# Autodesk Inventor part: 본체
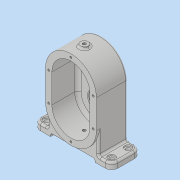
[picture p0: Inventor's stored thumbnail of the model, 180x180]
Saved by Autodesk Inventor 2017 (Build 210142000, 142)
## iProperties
Part Number: 본체
Material: 일반
Document SubType Name: Modeling
Designer: MRC
Density: 1 g/cm^3
Appearance: 기본값
Author: MRC
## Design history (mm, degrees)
sketch "스케치1"
  geometry: L1 (0, 0)-(0, 45); L2 (-40, 0)-(-40, 45); L3 (40, 45)-(40, 0); A1 r 40 centre (0, 0) between (-40, 0) and (40, 0); A2 r 40 centre (0, 45) between (40, 45) and (-40, 45); 1 further point
  constraints: 8 end point, 4 point on circle, 4 tangent, 2 centre point, 1 midpoint, 1 parallel, 1 vertical
  dimensions: "d0" = 45 distance of L1.start L1.end; "d1" = 80 distance between parallel lines of L3 L2
extrude "돌출1" new body sketch "스케치1" stored distance "d2" = 49; taper "d3" = 0 deg
sketch "스케치2"
  geometry: L1 (0, 45)-(0, 0); L2 (-26, 45)-(-26, 0); L3 (26, 0)-(26, 45); A1 r 40 centre (0, 45) between (40, 45) and (-40, 45) reference; A2 r 40 centre (0, 0) between (-40, 0) and (40, 0) reference; A3 r 26 centre (0, 45) between (26, 45) and (-26, 45); A4 r 26 centre (0, 0) between (-26, 0) and (26, 0); 1 further point
  constraints: 8 end point, 4 point on circle, 4 tangent, 2 centre point, 1 midpoint, 1 parallel, 1 vertical
  dimensions: "d4" = 52 distance between parallel lines of L3 L2
extrude "돌출2" join sketch "스케치2" distance "d5" = 8; taper "d6" = 0 deg
sketch "스케치3"
  geometry: L1 (0, 0)-(0, 45); L2 (-26, 0)-(-26, 15); L3 (26, 15)-(26, 0); L4 (-26, 0)-(-26, 45) reference; L5 (-26, 15)-(26, 15); L6 (26, 45)-(26, 0) reference; A1 r 26 centre (0, 0) between (-26, 0) and (26, 0) reference; A2 r 26 centre (0, 0) between (-26, 0) and (26, 0); 1 further point
  constraints: 10 end point, 2 point on circle, 2 point on line, 2 tangent, 1 centre point, 1 midpoint, 1 parallel, 1 vertical
  dimensions: "d7" = 30 distance from line of L1.end L5; "d8" = 52 distance of L2.end L3.start
extrude "돌출3" join sketch "스케치3" distance "d9" = 3; taper "d10" = 0 deg
node "작업 평면1"
sketch "스케치4"
  geometry: L1 (40, 24.5)-(-40, 24.5) reference; C1 r 6 at (0, 3.5); 1 further point
  constraints: 1 centre point, 1 vertical alignment
  dimensions: "d12" = 12 diameter of C1; "d14" = 21 distance from line of L1 C1.centre
extrude "돌출4" join sketch "스케치4" stored distance "d15" = 3; taper "d16" = 0 deg
sketch "스케치6"
  geometry: L1 (-40, 45)-(-40, 0) reference; L2 (40, 0)-(40, 45) reference; L3 (-30, 45)-(-30, 0); L4 (30, 0)-(30, 45); A1 r 40 centre (0, 0) between (-40, 0) and (40, 0) reference; A2 r 40 centre (0, 45) between (40, 45) and (-40, 45) reference; A3 r 30 centre (0, 0) between (-30, 0) and (30, 0); A4 r 30 centre (0, 45) between (30, 45) and (-30, 45)
  constraints: 4 end point, 4 point on circle, 2 centre point, 3 other
  dimensions: "d22" = 30 radius of A4
extrude "돌출5" cut sketch "스케치6" distance "d23" = 41; taper "d24" = 0 deg
hole "구멍1" diameter "d27" = 22; stored, may be unused: countersink angle "d31" = 90 deg, drill point angle "d33" = 118 deg; dims "d25" = 10, "d26" = 10, "d28" = 6, "d29" = 28, "d30" = 8, "d32" = 8
hole "구멍2" diameter "d36" = 20; stored, may be unused: countersink angle "d40" = 90 deg, drill point angle "d42" = 0 deg; dims "d34" = 10, "d35" = 10, "d37" = 6, "d38" = 28, "d39" = 8, "d41" = 12
sketch "스케치7"
  geometry: C1 r 11 at (0, 45) reference; C2 r 14 at (0, 45); A1 r 26 centre (0, 45) between (26, 45) and (-26, 45) reference; 1 further point
  constraints: 1 centre point, 1 coincident
  dimensions: "d43" = 28 diameter of C2
extrude "돌출6" cut sketch "스케치7" distance "d44" = 4; taper "d45" = 0 deg
sketch "스케치8"
  geometry: C1 r 14 at (0, 45) reference; A1 r 40 centre (0, 45) between (40, 45) and (-40, 45) reference; 2 further points
  constraints: 1 vertical alignment
  dimensions: "d46" = 20 distance of A1.centre point (0, 65)
hole "구멍3" sketch "스케치8" at (0, 65) diameter "d47" = 3.242; stored, may be unused: countersink angle "d51" = 90 deg, drill point angle "d53" = 118 deg; dims "d48" = 8, "d49" = 28, "d50" = 8, "d52" = 10
hole "구멍4" diameter "d59" = 4.917; stored, may be unused: countersink angle "d63" = 90 deg, drill point angle "d65" = 118 deg; dims "d57" = 10, "d58" = 10, "d60" = 12, "d61" = 28, "d62" = 8, "d64" = 17.1
sketch "스케치9"
  geometry: L1 (40, 0)-(40, 45) reference; L2 (-40, 45)-(-40, 0) reference; L3 (-40, 0)-(-40, -37); L4 (-40, -37)-(-61, -37); L5 (-61, -37)-(-61, -47); L6 (-61, -47)-(-35, -47); L7 (-35, -47)-(-35, -42); L8 (-35, -42)-(35, -42); L9 (35, -42)-(35, -47); L10 (35, -47)-(61, -47); L11 (61, -47)-(61, -37); L12 (61, -37)-(40, -37); L13 (40, -37)-(40, 0); A1 r 26 centre (0, 0) between (-26, 0) and (26, 0) reference; A2 r 40 centre (0, 0) between (-40, 0) and (40, 0) reference
  constraints: 22 end point, 8 perpendicular, 4 collinear, 4 point on line, 2 point on circle, 1 vertical
  dimensions: "d66" = 70 distance of L7.end L8.end; "d67" = 47 distance from line of L6 A1.centre; "d68" = 10 distance of L4.end L5.end; "d69" = 5 distance of L6.end L7.end; "d70" = 122 distance between parallel lines of L11 L5
extrude "돌출7" join sketch "스케치9" distance "d71" = 46; taper "d72" = 0 deg
fillet "모깎기1" dims "d73" = 10
hole "구멍5" diameter "d76" = 6.6; stored, may be unused: countersink angle "d80" = 90 deg, drill point angle "d82" = 118 deg; dims "d74" = 10, "d75" = 10, "d77" = 12, "d78" = 11, "d79" = 2, "d81" = 17.1
hole "구멍6" diameter "d85" = 6.6; stored, may be unused: countersink angle "d89" = 90 deg, drill point angle "d91" = 118 deg; dims "d83" = 10, "d84" = 10, "d86" = 12, "d87" = 11, "d88" = 2, "d90" = 17.1
hole "구멍7" diameter "d94" = 6.6; stored, may be unused: countersink angle "d98" = 90 deg, drill point angle "d100" = 118 deg; dims "d92" = 10, "d93" = 10, "d95" = 12, "d96" = 11, "d97" = 2, "d99" = 17.1
hole "구멍8" diameter "d103" = 6.6; stored, may be unused: countersink angle "d107" = 90 deg, drill point angle "d109" = 118 deg; dims "d101" = 10, "d102" = 10, "d104" = 12, "d105" = 11, "d106" = 2, "d108" = 17.1
sketch "스케치10"
  geometry: L1 (75, 49)-(-5, 49) reference; 2 further points
  constraints: 1 vertical alignment
  dimensions: "d110" = 21 distance from line of point (35, 28) L1
hole "구멍9" sketch "스케치10" at (35, 28) diameter "d111" = 4.917; stored, may be unused: countersink angle "d115" = 90 deg, drill point angle "d117" = 118 deg; dims "d112" = 12, "d113" = 12, "d114" = 1, "d116" = 17.1
sketch "스케치11"
  geometry: L1 (-30, 0)-(-30, 45) reference; L2 (30, 45)-(30, 0) reference; L3 (-35, 45)-(-35, 0); L4 (35, 0)-(35, 45); A1 r 30 centre (0, 0) between (-30, 0) and (30, 0) reference; A2 r 30 centre (0, 45) between (30, 45) and (-30, 45) reference; A3 r 35 centre (0, 0) between (-35, 0) and (35, 0); A4 r 35 centre (0, 45) between (35, 45) and (-35, 45); 6 further points
  constraints: 6 point on circle, 4 coincident, 4 end point, 2 centre point, 3 other
  dimensions: "d118" = 35 radius of A4
hole "구멍10" sketch "스케치11" at (0, 80), (35, 45), (-35, 45), (-35, 0), (0, -35), (35, 0) diameter "d119" = 3.242; stored, may be unused: countersink angle "d123" = 90 deg, drill point angle "d125" = 118 deg; dims "d120" = 8, "d121" = 12, "d122" = 1, "d124" = 10
chamfer "모따기1" distance "d126" = 1; stored, may be unused: second distance "d127" = 2, angle "d128" = 45 deg
fillet "모깎기2" dims "d129" = 3
fillet "모깎기3" dims "d130" = 3
fillet "모깎기4" dims "d131" = 5
sketch "스케치12"
  geometry: L1 (-51, -47)-(-61, -47) reference; A1 r 37 centre (0, 45) between (37, 45) and (-37, 45) reference; 1 further point
  constraints: 1 vertical alignment, 1 other
  dimensions: "d132" = 12 distance from line of point (0, -35) L1
feature "엠보싱1" sketch "스케치12" dims "d0" = 45, "d1" = 80, "d133" = 0.5, "d134" = 0
fillet "모깎기5" dims "d135" = 0.3
node "솔리드1"
pattern_circular "원형 패턴1" dims angle "d55" = 360 deg
other parameters: "d11" = 88
